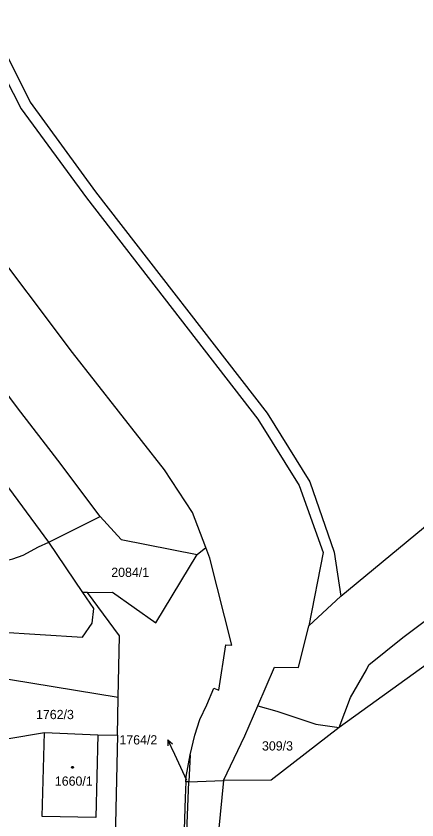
# Model space of a CAD drawing. Extents: x -679220 to -673243, y -1075091 to -1066557.
# Drawn here: x -676494.4 to -676420.8, y -1072401 to -1072253.3 of the extents above; entities that cross this region are included whole.
import ezdxf

# ---------------------------------------------------------------- set-up
doc = ezdxf.new("R2010")
doc.units = 0
for name, color, linetype in [('Hranice parcel', 7, 'Continuous'), ('Parcelní čísla', 7, 'Continuous'), ('Pop  PČ popisy', 7, 'Continuous'), ('Značky budov', 7, 'Continuous')]:
    doc.layers.add(name, color=color, linetype=linetype)

msp = doc.modelspace()

# ---------------------------------------------------------------- linework, layer by layer
at = {"layer": 'Hranice parcel'}
for p, q in [((-676488.44, -1072349.97), (-676478.96, -1072345.25)), ((-676482.17, -1072359.23), (-676488.44, -1072349.97)), ((-676461.14, -1072352.25), (-676459.56, -1072350.97)), ((-676397.84, -1072357.19), (-676435.06, -1072384.05)), ((-676481.31, -1072359.23), (-676482.17, -1072359.23)), ((-676440.64, -1072365.35), (-676434.8, -1072359.89)), ((-676475.83, -1072385.47), (-676475.69, -1072378.53)), ((-676489.23, -1072385), (-676479.41, -1072385.41)), ((-676479.41, -1072385.41), (-676475.83, -1072385.47)), ((-676475.83, -1072385.47), (-676476.33, -1072409.48)), ((-676462.47, -1072389.11), (-676462.68, -1072394.04)), ((-676462.68, -1072394.04), (-676463.24, -1072394.05)), ((-676462.68, -1072394.04), (-676456.33, -1072393.82))]:
    msp.add_line(p, q, dxfattribs=at)
for points in [[(-676541.89, -1072018.69), (-676528.74, -1072032.82), (-676518.66, -1072044.42), (-676511.2, -1072056.95), (-676505.9, -1072070.52), (-676502.09, -1072084.93), (-676501.62, -1072096.94), (-676502.1, -1072114.34), (-676501.22, -1072116.73), (-676500.34, -1072121.98), (-676502.88, -1072124.51), (-676503.32, -1072130.04), (-676504.31, -1072153.57), (-676506.28, -1072192.84), (-676507.47, -1072212.67), (-676507.15, -1072233.46), (-676502.3, -1072253.2), (-676493.52, -1072270.33), (-676481.52, -1072286.7), (-676450.04, -1072327.35), (-676442.42, -1072339.58), (-676438, -1072351.9), (-676440.64, -1072365.35)], [(-676498.25, -1072121.48), (-676501.4, -1072130.67), (-676502.29, -1072153.75), (-676504.21, -1072193.03), (-676505.46, -1072212.8), (-676505.16, -1072233.19), (-676500.12, -1072252.58), (-676491.86, -1072269.13), (-676479.84, -1072285.61), (-676448.34, -1072326.26), (-676440.47, -1072338.92), (-676436.01, -1072351.82), (-676434.8, -1072359.89)], [(-676459.56, -1072350.97), (-676462.01, -1072344.52), (-676467.19, -1072336.72), (-676484.08, -1072315.1), (-676500.58, -1072293.17), (-676511.67, -1072277.21), (-676520.52, -1072259.37), (-676526.16, -1072238.16), (-676527.35, -1072218.91), (-676525.48, -1072188.37), (-676523.69, -1072157.38), (-676522.2, -1072127.02), (-676522, -1072124.37)], [(-676478.96, -1072345.25), (-676486.76, -1072334.9), (-676494.15, -1072325.32), (-676502.31, -1072314.41), (-676514.96, -1072297.26), (-676522.29, -1072287.64), (-676529.49, -1072277.98), (-676533.98, -1072271.49), (-676535.89, -1072267.87), (-676539.19, -1072260.61), (-676540.03, -1072256.53), (-676540.61, -1072252.56), (-676541.33, -1072240.55), (-676542.21, -1072228.4), (-676543.04, -1072216.44), (-676543.58, -1072204.41), (-676544.01, -1072192.29), (-676544.34, -1072180.34), (-676543.76, -1072168.24), (-676542.51, -1072160.31), (-676535.08, -1072128.13)], [(-676434.8, -1072359.89), (-676415.01, -1072343.53), (-676389.18, -1072322.47), (-676377.87, -1072305.66), (-676370.95, -1072288.33), (-676368.5, -1072263.86), (-676369.03, -1072238.4), (-676368.85, -1072231.56)], [(-676488.44, -1072349.97), (-676502.98, -1072330.28), (-676506.94, -1072323.45)], [(-676478.96, -1072345.25), (-676475.14, -1072349.5), (-676461.14, -1072352.25)], [(-676518.84, -1072354.84), (-676514.96, -1072354.66), (-676508.93, -1072354.55), (-676504.17, -1072354.34), (-676501.94, -1072354.24), (-676500.6, -1072354.18), (-676499.09, -1072354.05), (-676495.02, -1072353.07), (-676493.1, -1072352.38), (-676490.29, -1072350.84), (-676488.44, -1072349.97)], [(-676462.47, -1072389.11), (-676461.58, -1072385.46), (-676460.68, -1072382.56), (-676459.41, -1072379.91), (-676458.12, -1072376.82), (-676457.18, -1072377.2), (-676455.93, -1072368.87), (-676454.82, -1072368.9), (-676458.82, -1072352.92), (-676459.56, -1072350.97)], [(-676481.31, -1072359.23), (-676476.75, -1072359.19), (-676468.79, -1072364.83), (-676461.14, -1072352.25)], [(-676435.06, -1072384.05), (-676433.01, -1072378.55), (-676430.04, -1072373.48), (-676429.61, -1072372.52), (-676423.37, -1072367.5), (-676406.48, -1072354.84), (-676405.02, -1072354.26)], [(-676521.19, -1072365.02), (-676482.21, -1072367.44), (-676480.46, -1072364.89), (-676480.16, -1072362.19), (-676482.17, -1072359.23)], [(-676475.69, -1072378.53), (-676475.46, -1072367.19), (-676481.31, -1072359.23)], [(-676450.01, -1072380.05), (-676446.94, -1072372.97), (-676442.58, -1072373.04), (-676440.64, -1072365.35)], [(-676475.69, -1072378.53), (-676495.46, -1072375.29), (-676519.85, -1072371.33), (-676529.25, -1072369.16)], [(-676456.33, -1072393.82), (-676452.42, -1072385.61), (-676450.01, -1072380.05)], [(-676450.01, -1072380.05), (-676446.53, -1072381.07), (-676439.38, -1072383.46), (-676435.06, -1072384.05)], [(-676435.06, -1072384.05), (-676447.57, -1072393.72), (-676456.33, -1072393.82)], [(-676496.99, -1072386.47), (-676496.16, -1072386.14), (-676489.23, -1072385)], [(-676479.41, -1072385.41), (-676479.76, -1072400.62), (-676489.62, -1072400.4), (-676489.23, -1072385)], [(-676463.24, -1072394.05), (-676463.17, -1072393.08), (-676462.47, -1072389.11)], [(-676463.24, -1072394.05), (-676463.35, -1072396.96), (-676465.03, -1072449.76), (-676465.64, -1072463.77), (-676474.82, -1072551.78), (-676474.47, -1072554.88), (-676473.01, -1072557.18), (-676471.19, -1072559.31), (-676468.12, -1072561.69), (-676465.95, -1072562.73), (-676464.91, -1072562.82)], [(-676463.01, -1072562.26), (-676461.92, -1072551.65), (-676463.98, -1072549.73), (-676464.18, -1072517.79), (-676462.45, -1072516.5), (-676460.17, -1072487.09), (-676455.96, -1072472.11), (-676453.9, -1072467.48), (-676452.8, -1072460.8), (-676453.72, -1072452.74), (-676456.41, -1072444.8), (-676463.15, -1072435.69), (-676463.19, -1072429.96), (-676462.52, -1072423.4), (-676461, -1072417.1), (-676463.33, -1072409.42), (-676462.68, -1072394.04)], [(-676456.33, -1072393.82), (-676457.23, -1072403.17), (-676455, -1072408.82)]]:
    msp.add_lwpolyline(points, dxfattribs=at)
at = {"layer": 'Pop  PČ popisy'}
for p, q in [((-676466.55, -1072386.33), (-676466.58, -1072387.45)), ((-676465.28, -1072389.05), (-676466.55, -1072386.33)), ((-676466.55, -1072386.33), (-676465.67, -1072387.03)), ((-676463.04, -1072393.83), (-676465.28, -1072389.05))]:
    msp.add_line(p, q, dxfattribs=at)
at = {"layer": 'Značky budov'}
msp.add_circle((-676484.05, -1072391.38), 0.175, dxfattribs=at)

# ---------------------------------------------------------------- texts
at = {"layer": 'Parcelní čísla'}
for s, p in [('2084/1', (-676476.95, -1072356.38)), ('1762/3', (-676490.77, -1072382.52)), ('1764/2', (-676475.45, -1072387.18)), ('309/3', (-676449.26, -1072388.29)), ('1660/1', (-676487.31, -1072394.76))]:
    msp.add_text(s, height=1.7, dxfattribs=at).set_placement(p)

doc.saveas('drawing.dxf')
